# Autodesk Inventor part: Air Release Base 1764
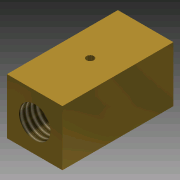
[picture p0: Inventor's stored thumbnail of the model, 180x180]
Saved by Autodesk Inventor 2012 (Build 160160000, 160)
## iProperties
Created: 2010-02
Part Number: Air Release Base 1764
Document SubType Name: Modeling
Designer: jgehrig
Density: 1 g/cm^3
Material: Default
Author: jgehrig
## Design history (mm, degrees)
sketch "Sketch1"
  geometry: L1 (-32.869, 12)-(-13.819, 12); L2 (-13.819, 12)-(-13.819, -7.05); L3 (-13.819, -7.05)-(-32.869, -7.05); L4 (-32.869, -7.05)-(-32.869, 12); C1 r 5.397 at (-23.344, 2.475); 1 further point
  constraints: 8 end point, 2 parallel, 1 centre point, 1 horizontal, 1 perpendicular
  dimensions: "d0" = 19.05 distance of L1.start L1.end; "d1" = 19.05 distance of L1.end L2.end; "d2" = 10.795 diameter of C1
extrude "Extrusion1" new body sketch "Sketch1" distance "d3" = 38.1; taper "d4" = 0 deg
sketch "Sketch2"
  geometry: C1 r 1.27 at (9.525, -19.05); 1 further point
  constraints: 1 centre point
  dimensions: "d5" = 2.54 diameter of C1
extrude "Extrusion2" cut sketch "Sketch2" distance "d6" = 6.35; taper "d7" = 0 deg
thread "Thread1" dims "d8" = 25.4, "d9" = 0
body "Solid1"
